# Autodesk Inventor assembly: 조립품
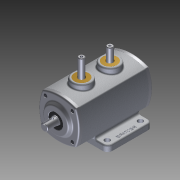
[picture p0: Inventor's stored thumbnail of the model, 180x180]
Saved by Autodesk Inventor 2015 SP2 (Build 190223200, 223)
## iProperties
Created: 2015-06
Part Number: 조립품
Document SubType Name: Assembly
Designer: AMC
Mass: 849.52 g
Surface Area: 1894.53 cm^2
Volume: 720.806 cm^3
Density: 1.17857 g/cm^3
Author: AMC
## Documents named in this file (12)
- C:\Users\AMC\Desktop\350620V1008\조립품-350620V1008.iam
- C:\Users\AMC\Desktop\350620V1008\M4-소켓머리.ipt
- C:\Users\AMC\Desktop\350620V1008\뒷커버.ipt
- C:\Users\AMC\Desktop\350620V1008\베어링 6203.ipt
- C:\Users\AMC\Desktop\350620V1008\본체.ipt
- C:\Users\AMC\Desktop\350620V1008\부시.ipt
- C:\Users\AMC\Desktop\350620V1008\스프링10.ipt
- C:\Users\AMC\Desktop\350620V1008\스프링11.ipt
- C:\Users\AMC\Desktop\350620V1008\슬라이더.ipt
- C:\Users\AMC\Desktop\350620V1008\앞커버.ipt
- C:\Users\AMC\Desktop\350620V1008\오일실.ipt
- C:\Users\AMC\Desktop\350620V1008\축.ipt
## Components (11 placed, 3 different names)
1. 7-베어링 6203:1
2. 8-오일실:1
3. 7-베어링 6203:2
4. 9-M4-소켓머리:1
5. 9-M4-소켓머리:3
6. 9-M4-소켓머리:4
7. 9-M4-소켓머리:5
8. 9-M4-소켓머리:2
9. 9-M4-소켓머리:6
10. 9-M4-소켓머리:7
11. 9-M4-소켓머리:8
